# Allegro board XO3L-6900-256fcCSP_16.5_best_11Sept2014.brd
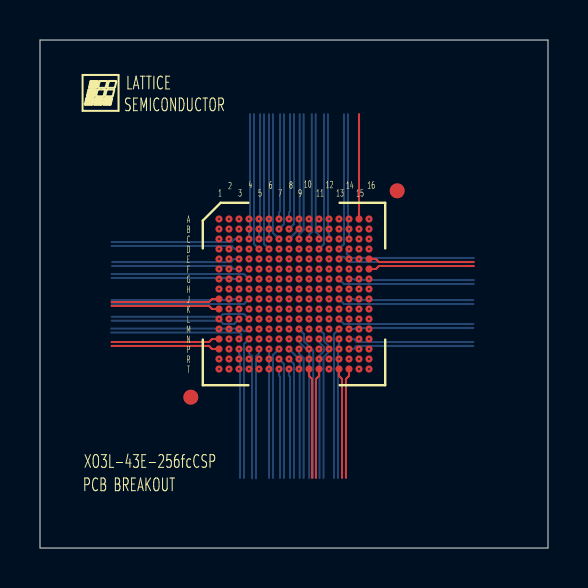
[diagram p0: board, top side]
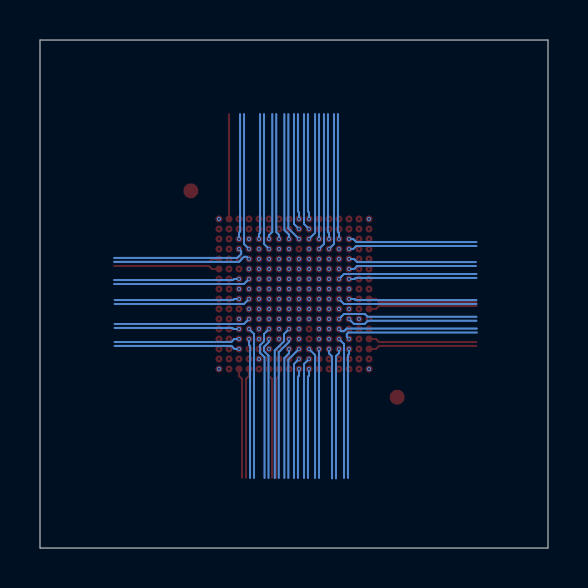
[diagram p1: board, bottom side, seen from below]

Outline 25.4 x 25.4 mm; copper layers: TOP, L2_GND, L3_SIGNAL1, L4_SIGNAL2, L5_PWR, BOTTOM. Coordinates in mm from the lower left corner of the outline.
Outline path: 0,25.4 25.4,25.4 25.4,0 0,0 0,25.4

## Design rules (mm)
constraint set DEFAULT: min track width 0.102, pair gap 0.097
net group CDPB4: nets PB4C PB4D
net group CDPB13: nets PB13C PB13D
net group CDPB18: nets PB18C PB18D
net group CDPB26: nets PB26C PB26D
net group CDPB31: nets PB31C PB31D
net group CDPB38: nets PB38C PB38D
net group CDPL2: nets PL2C PL2D
net group CDPL4: nets PL4C PL4D
net group CDPL6: nets PL6C PL6D
net group CDPL7: nets PL7C PL7D
net group CDPL9: nets PL9C PL9D
net group CDPL10: nets PL10C PL10D
net group CDPL15: nets PL15C PL15D
net group CDPL16: nets PL16C PL16D
net group CDPL19: nets PL19C PL19D
net group CDPL21: nets PL21C PL21D
net group CDPL23: nets PL23C PL23D
net group CDPL25: nets PL25C PL25D
net group CDPR2: nets PR2C PR2D
net group CDPR4: nets PR4C PR4D
net group CDPR6: nets PR6C PR6D
net group CDPR7: nets PR7C PR7D
net group CDPR10: nets PR10C PR10D
net group CDPR11: nets PR11C PR11D
net group CDPR16: nets PR16C PR16D
net group CDPR17: nets PR17C PR17D
net group CDPR19: nets PR19C PR19D
net group CDPR21: nets PR21C PR21D
net group CDPR23: nets PR23C PR23D
net group CDPR24: nets PR24A PR24B
net group CDPR25: nets PR25C PR25D
net group CDPT14: nets PT14C PT14D
net group CDPT17: nets PT17C PT17D
net group CDPT22: nets PT22C PT22D
net group CDPT27: nets PT27C PT27D
net group CDPT36: nets PT36C PT36D
net group PB4: nets PB4A PB4B
net group PB6: nets PB6A PB6B
net group PB7: nets PB7A PB7B
net group PB9: nets PB9A PB9B
net group PB10: nets PB10A PB10B
net group PB12: nets PB12A PB12B
net group PB13: nets PB13A PB13B
net group PB15: nets PB15A PB15B
net group PB16: nets PB16A PB16B
net group PB18: nets PB18A PB18B
net group PB21: nets PB21A PB21B
net group PB23: nets PB23A PB23B
net group PB26: nets PB26A PB26B
net group PB28: nets PB28A PB28B
net group PB29: nets PB29A PB29B
net group PB31: nets PB31A PB31B
net group PB34: nets PB34A PB34B
net group PB35: nets PB35A PB35B
net group PB37: nets PB37A PB37B
net group PB38: nets PB38A PB38B
net group PL3: nets PL3A PL3B
net group PL4: nets PL4A PL4B
net group PL6: nets PL6A PL6B
net group PL8: nets PL8A PL8B
net group PL9: nets PL9A PL9B
net group PL10: nets PL10A PL10B
net group PL11: nets PL11A PL11B
net group PL12: nets PL12A PL12B
net group PL15: nets PL15A PL15B
net group PL17: nets PL17A PL17B
net group PL19: nets PL19A PL19B
net group PL22: nets PL22A PL22B
net group PL24: nets PL24A PL24B
net group PL25: nets PL25A PL25B
net group PR2: nets PR2A PR2B
net group PR3: nets PR3A PR3B
net group PR5: nets PR5A PR5B
net group PR7: nets PR7A PR7B
net group PR9: nets PR9A PR9B
net group PR11: nets PR11A PR11B
net group PR12: nets PR12A PR12B
net group PR15: nets PR15A PR15B
net group PR16: nets PR16A PR16B
net group PR17: nets PR17A PR17B
net group PR18: nets PR18A PR18B
net group PR21: nets PR21A PR21B
net group PR23: nets PR23A PR23B
net group PT9: nets PT9A PT9B
net group PT10: nets PT10A PT10B
net group PT11: nets PT11A PT11B
net group PT12: nets PT12A PT12B
net group PT14: nets PT14A PT14B
net group PT15: nets PT15A PT15B
net group PT16: nets PT16A PT16B
net group PT17: nets PT17A PT17B
net group PT18: nets PT18A PT18B
net group PT21: nets PT21A PT21B
net group PT22: nets PT22A PT22B
net group PT25: nets PT25A PT25B
net group PT26: nets PT26A PT26B
net group PT27: nets PT27A PT27B
net group PT28: nets PT28A PT28B
net group PT32: nets PT32A PT32B
net group PT33: nets PT33A PT33B
net group PT34: nets PT34A PT34B
net group PT35: nets PT35A PT35B
net group PT36: nets PT36A PT36B

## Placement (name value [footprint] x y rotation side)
BGA  -  [BGA256C50P16X16_900X900X100B-1]  12.7 12.7 270 top
NOREF  -  []  1.85 21.54 0 top

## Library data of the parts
BGA = BGA256C50P16X16_900X900X100B-1

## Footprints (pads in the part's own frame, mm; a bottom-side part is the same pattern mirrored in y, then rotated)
BGA256C50P16X16_900X900X100B-1
  round 0.75 smd: (-5.16,5.16) (5.16,-5.16)
  round 0.356 smd: A1(-3.75,-3.75) A2(-3.75,-3.25) A3(-3.75,-2.75) A4(-3.75,-2.25) A5(-3.75,-1.75) A6(-3.75,-1.25) A7(-3.75,-0.75) A8(-3.75,-0.25) A9(-3.75,0.25) A10(-3.75,0.75) A11(-3.75,1.25) A12(-3.75,1.75) A13(-3.75,2.25) A14(-3.75,2.75) A15(-3.75,3.25) A16(-3.75,3.75) B1(-3.25,-3.75) B2(-3.25,-3.25) B3(-3.25,-2.75) B4(-3.25,-2.25) B5(-3.25,-1.75) B6(-3.25,-1.25) B7(-3.25,-0.75) B8(-3.25,-0.25) B9(-3.25,0.25) B10(-3.25,0.75) B11(-3.25,1.25) B12(-3.25,1.75) B13(-3.25,2.25) B14(-3.25,2.75) B15(-3.25,3.25) B16(-3.25,3.75) C1(-2.75,-3.75) C2(-2.75,-3.25) C3(-2.75,-2.75) C4(-2.75,-2.25) C5(-2.75,-1.75) C6(-2.75,-1.25) C7(-2.75,-0.75) C8(-2.75,-0.25) C9(-2.75,0.25) C10(-2.75,0.75) C11(-2.75,1.25) C12(-2.75,1.75) C13(-2.75,2.25) C14(-2.75,2.75) C15(-2.75,3.25) C16(-2.75,3.75) D1(-2.25,-3.75) D2(-2.25,-3.25) D3(-2.25,-2.75) D4(-2.25,-2.25) D5(-2.25,-1.75) D6(-2.25,-1.25) D7(-2.25,-0.75) D8(-2.25,-0.25) D9(-2.25,0.25) D10(-2.25,0.75) D11(-2.25,1.25) D12(-2.25,1.75) D13(-2.25,2.25) D14(-2.25,2.75) D15(-2.25,3.25) D16(-2.25,3.75) E1(-1.75,-3.75) E2(-1.75,-3.25) E3(-1.75,-2.75) E4(-1.75,-2.25) E5(-1.75,-1.75) E6(-1.75,-1.25) E7(-1.75,-0.75) E8(-1.75,-0.25) E9(-1.75,0.25) E10(-1.75,0.75) E11(-1.75,1.25) E12(-1.75,1.75) E13(-1.75,2.25) E14(-1.75,2.75) E15(-1.75,3.25) E16(-1.75,3.75) F1(-1.25,-3.75) F2(-1.25,-3.25) F3(-1.25,-2.75) F4(-1.25,-2.25) F5(-1.25,-1.75) F6(-1.25,-1.25) F7(-1.25,-0.75) F8(-1.25,-0.25) F9(-1.25,0.25) F10(-1.25,0.75) F11(-1.25,1.25) F12(-1.25,1.75) F13(-1.25,2.25) F14(-1.25,2.75) F15(-1.25,3.25) F16(-1.25,3.75) G1(-0.75,-3.75) G2(-0.75,-3.25) G3(-0.75,-2.75) G4(-0.75,-2.25) G5(-0.75,-1.75) G6(-0.75,-1.25) G7(-0.75,-0.75) G8(-0.75,-0.25) G9(-0.75,0.25) G10(-0.75,0.75) G11(-0.75,1.25) G12(-0.75,1.75) G13(-0.75,2.25) G14(-0.75,2.75) G15(-0.75,3.25) G16(-0.75,3.75) H1(-0.25,-3.75) H2(-0.25,-3.25) H3(-0.25,-2.75) H4(-0.25,-2.25) H5(-0.25,-1.75) H6(-0.25,-1.25) H7(-0.25,-0.75) H8(-0.25,-0.25) H9(-0.25,0.25) H10(-0.25,0.75) H11(-0.25,1.25) H12(-0.25,1.75) H13(-0.25,2.25) H14(-0.25,2.75) H15(-0.25,3.25) H16(-0.25,3.75) J1(0.25,-3.75) J2(0.25,-3.25) J3(0.25,-2.75) J4(0.25,-2.25) J5(0.25,-1.75) J6(0.25,-1.25) J7(0.25,-0.75) J8(0.25,-0.25) J9(0.25,0.25) J10(0.25,0.75) J11(0.25,1.25) J12(0.25,1.75) J13(0.25,2.25) J14(0.25,2.75) J15(0.25,3.25) J16(0.25,3.75) K1(0.75,-3.75) K2(0.75,-3.25) K3(0.75,-2.75) K4(0.75,-2.25) K5(0.75,-1.75) K6(0.75,-1.25) K7(0.75,-0.75) K8(0.75,-0.25) K9(0.75,0.25) K10(0.75,0.75) K11(0.75,1.25) K12(0.75,1.75) K13(0.75,2.25) K14(0.75,2.75) K15(0.75,3.25) K16(0.75,3.75) L1(1.25,-3.75) L2(1.25,-3.25) L3(1.25,-2.75) L4(1.25,-2.25) L5(1.25,-1.75) L6(1.25,-1.25) L7(1.25,-0.75) L8(1.25,-0.25) L9(1.25,0.25) L10(1.25,0.75) L11(1.25,1.25) L12(1.25,1.75) L13(1.25,2.25) L14(1.25,2.75) L15(1.25,3.25) L16(1.25,3.75) M1(1.75,-3.75) M2(1.75,-3.25) M3(1.75,-2.75) M4(1.75,-2.25) M5(1.75,-1.75) M6(1.75,-1.25) M7(1.75,-0.75) M8(1.75,-0.25) M9(1.75,0.25) M10(1.75,0.75) M11(1.75,1.25) M12(1.75,1.75) M13(1.75,2.25) M14(1.75,2.75) M15(1.75,3.25) M16(1.75,3.75) N1(2.25,-3.75) N2(2.25,-3.25) N3(2.25,-2.75) N4(2.25,-2.25) N5(2.25,-1.75) N6(2.25,-1.25) N7(2.25,-0.75) N8(2.25,-0.25) N9(2.25,0.25) N10(2.25,0.75) N11(2.25,1.25) N12(2.25,1.75) N13(2.25,2.25) N14(2.25,2.75) N15(2.25,3.25) N16(2.25,3.75) P1(2.75,-3.75) P2(2.75,-3.25) P3(2.75,-2.75) P4(2.75,-2.25) P5(2.75,-1.75) P6(2.75,-1.25) P7(2.75,-0.75) P8(2.75,-0.25) P9(2.75,0.25) P10(2.75,0.75) P11(2.75,1.25) P12(2.75,1.75) P13(2.75,2.25) P14(2.75,2.75) P15(2.75,3.25) P16(2.75,3.75) R1(3.25,-3.75) R2(3.25,-3.25) R3(3.25,-2.75) R4(3.25,-2.25) R5(3.25,-1.75) R6(3.25,-1.25) R7(3.25,-0.75) R8(3.25,-0.25) R9(3.25,0.25) R10(3.25,0.75) R11(3.25,1.25) R12(3.25,1.75) R13(3.25,2.25) R14(3.25,2.75) R15(3.25,3.25) R16(3.25,3.75) T1(3.75,-3.75) T2(3.75,-3.25) T3(3.75,-2.75) T4(3.75,-2.25) T5(3.75,-1.75) T6(3.75,-1.25) T7(3.75,-0.75) T8(3.75,-0.25) T9(3.75,0.25) T10(3.75,0.75) T11(3.75,1.25) T12(3.75,1.75) T13(3.75,2.25) T14(3.75,2.75) T15(3.75,3.25) T16(3.75,3.75)

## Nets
GND: BGA.A1 BGA.A16 BGA.F5 BGA.F10 BGA.G7 BGA.G8 BGA.G9 BGA.G10 BGA.G11 BGA.H6 BGA.H11 BGA.J6 BGA.J11 BGA.K5 BGA.K6 BGA.K7 BGA.K8 BGA.K9 BGA.K10 BGA.K11 BGA.K12 BGA.L6 BGA.T1 BGA.T16
VCC: BGA.H7 BGA.H8 BGA.H9 BGA.H10 BGA.J7 BGA.J8 BGA.J9 BGA.J10
VCCIO0: BGA.F6 BGA.F7 BGA.F8 BGA.F9
VCCIO1: BGA.G6 BGA.H5 BGA.J5
VCCIO2: BGA.L7 BGA.L8 BGA.L9 BGA.L10
VCCIO3: BGA.L11 BGA.L12
VCCIO4: BGA.H12 BGA.J12
VCCIO5: BGA.F11 BGA.G12
PB4A: BGA.P13
PB4B: BGA.R14
PB4C: BGA.N12
PB4D: BGA.M12
PB6A: BGA.T13
PB6B: BGA.T14
PB7A: BGA.P12
PB7B: BGA.R13
PB9A: BGA.M11
PB9B: BGA.N11
PB10A: BGA.R12
PB10B: BGA.P11
PB12A: BGA.T12
PB12B: BGA.R11
PB13A: BGA.N10
PB13B: BGA.M10
PB13C: BGA.P10
PB13D: BGA.R10
PB15A: BGA.T11
PB15B: BGA.T10
PB16A: BGA.T9
PB16B: BGA.R9
PB18A: BGA.N9
PB18B: BGA.M9
PB18C: BGA.P9
PB18D: BGA.P8
PB21A: BGA.R8
PB21B: BGA.T8
PB23A: BGA.T7
PB23B: BGA.R7
PB26A: BGA.N8
PB26B: BGA.M8
PB26C: BGA.T6
PB26D: BGA.R6
PB28A: BGA.P7
PB28B: BGA.P6
PB29A: BGA.T5
PB29B: BGA.R5
PB31A: BGA.N7
PB31B: BGA.M7
PB31C: BGA.T4
PB31D: BGA.R4
PB34A: BGA.R3
PB34B: BGA.T3
PB35A: BGA.M6
PB35B: BGA.N6
PB37A: BGA.R2
PB37B: BGA.T2
PB38A: BGA.M5
PB38B: BGA.N5
PB38C: BGA.P5
PB38D: BGA.P4
PL2C: BGA.D13
PL2D: BGA.C14
PL3A: BGA.B15
PL3B: BGA.B16
PL4A: BGA.C15
PL4B: BGA.C16
PL4C: BGA.D14
PL4D: BGA.E13
PL6A: BGA.D15
PL6B: BGA.D16
PL6C: BGA.F13
PL6D: BGA.F12
PL7C: BGA.E15
PL7D: BGA.E14
PL8A: BGA.G13
PL8B: BGA.G14
PL9A: BGA.F14
PL9B: BGA.F15
PL9C: BGA.E16
PL9D: BGA.F16
PL10A: BGA.G15
PL10B: BGA.G16
PL10C: BGA.H13
PL10D: BGA.H14
PL11A: BGA.H15
PL11B: BGA.H16
PL12A: BGA.J16
PL12B: BGA.J15
PL15A: BGA.K16
PL15B: BGA.K15
PL15C: BGA.J13
PL15D: BGA.J14
PL16C: BGA.L16
PL16D: BGA.K14
PL17A: BGA.M16
PL17B: BGA.L15
PL19A: BGA.N16
PL19B: BGA.M15
PL19C: BGA.K13
PL19D: BGA.L14
PL21C: BGA.M14
PL21D: BGA.L13
PL22A: BGA.P16
PL22B: BGA.N15
PL23C: BGA.P15
PL23D: BGA.R16
PL24A: BGA.R15
PL24B: BGA.T15
PL25A: BGA.M13
PL25B: BGA.N13
PL25C: BGA.N14
PL25D: BGA.P14
PR2A: BGA.A2
PR2B: BGA.B2
PR2C: BGA.D4
PR2D: BGA.E4
PR3A: BGA.B1
PR3B: BGA.C2
PR4C: BGA.D3
PR4D: BGA.C3
PR5A: BGA.D2
PR5B: BGA.C1
PR6C: BGA.F4
PR6D: BGA.G5
PR7A: BGA.D1
PR7B: BGA.E2
PR7C: BGA.F3
PR7D: BGA.E3
PR9A: BGA.G4
PR9B: BGA.G3
PR10C: BGA.E1
PR10D: BGA.F2
PR11A: BGA.G2
PR11B: BGA.F1
PR11C: BGA.H4
PR11D: BGA.H3
PR12A: BGA.H2
PR12B: BGA.G1
PR15A: BGA.H1
PR15B: BGA.J2
PR16A: BGA.J1
PR16B: BGA.K1
PR16C: BGA.J4
PR16D: BGA.J3
PR17A: BGA.K2
PR17B: BGA.L1
PR17C: BGA.L2
PR17D: BGA.K3
PR18A: BGA.M1
PR18B: BGA.M2
PR19C: BGA.K4
PR19D: BGA.L5
PR21A: BGA.N1
PR21B: BGA.P1
PR21C: BGA.L3
PR21D: BGA.L4
PR23A: BGA.M3
PR23B: BGA.N2
PR23C: BGA.R1
PR23D: BGA.P2
PR24A: BGA.N3
PR24B: BGA.M4
PR25C: BGA.P3
PR25D: BGA.N4
PT9A: BGA.A14
PT9B: BGA.B14
PT9C: BGA.A15
PT10A: BGA.E12
PT10B: BGA.E11
PT11A: BGA.A13
PT11B: BGA.B13
PT12A: BGA.C13
PT12B: BGA.D12
PT14A: BGA.E10
PT14B: BGA.D10
PT14C: BGA.D11
PT14D: BGA.C12
PT15A: BGA.B12
PT15B: BGA.A12
PT16A: BGA.A11
PT16B: BGA.B11
PT17A: BGA.B10
PT17B: BGA.A10
PT17C: BGA.C10
PT17D: BGA.C11
PT18A: BGA.B9
PT18B: BGA.A9
PT21A: BGA.E9
PT21B: BGA.D9
PT22A: BGA.C9
PT22B: BGA.C8
PT22C: BGA.A8
PT22D: BGA.B8
PT25A: BGA.D8
PT25B: BGA.E8
PT26A: BGA.B7
PT26B: BGA.A7
PT27A: BGA.D7
PT27B: BGA.E7
PT27C: BGA.C7
PT27D: BGA.C6
PT28A: BGA.A6
PT28B: BGA.B6
PT32A: BGA.A5
PT32B: BGA.B5
PT33A: BGA.D6
PT33B: BGA.C5
PT34A: BGA.E6
PT34B: BGA.E5
PT35A: BGA.A4
PT35B: BGA.B4
PT36A: BGA.A3
PT36B: BGA.B3
PT36C: BGA.C4
PT36D: BGA.D5

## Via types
v1: diameter 0.203, hole 0.102, TOP to BOTTOM, 148 vias
v2: diameter 0.203, hole 0.102, TOP to L3_SIGNAL1, 97 vias

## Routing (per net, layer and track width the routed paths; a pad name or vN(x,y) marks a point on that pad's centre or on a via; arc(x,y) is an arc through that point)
GND:
  vias: v1(8.95,16.45) v1(8.95,8.95) v1(10.95,13.95) v1(10.95,11.95) v1(11.45,12.95) v1(11.45,12.45) v1(11.45,11.95) v1(11.45,11.45) v1(11.95,13.45) v1(11.95,11.95) v1(12.45,13.45) v1(12.45,11.95) v1(12.95,13.45) v1(12.95,11.95) v1(13.45,13.95) v1(13.45,13.45) v1(13.45,11.95) v1(13.95,13.45) v1(13.95,12.95) v1(13.95,12.45) v1(13.95,11.95) v1(14.45,11.95) v1(16.45,16.45) v1(16.45,8.95)
VCC:
  vias: v1(11.95,12.95) v1(11.95,12.45) v1(12.45,12.95) v1(12.45,12.45) v1(12.95,12.95) v1(12.95,12.45) v1(13.45,12.95) v1(13.45,12.45)
VCCIO0:
  vias: v1(11.45,13.95) v1(11.95,13.95) v1(12.45,13.95) v1(12.95,13.95)
VCCIO1:
  vias: v1(10.95,12.95) v1(10.95,12.45) v1(11.45,13.45)
VCCIO2:
  vias: v1(11.95,11.45) v1(12.45,11.45) v1(12.95,11.45) v1(13.45,11.45)
VCCIO3:
  vias: v1(13.95,11.45) v1(14.45,11.45)
VCCIO4:
  vias: v1(14.45,12.95) v1(14.45,12.45)
VCCIO5:
  vias: v1(13.95,13.95) v1(14.45,13.45)
PB4A: length 6.5
  L3_SIGNAL1 w0.102: 15.2,3.51 15.2,9.7 v2(14.95,9.95)
PB4B: length 6
  L3_SIGNAL1 w0.102: 15.4,3.51 15.4,9.07 15.45,9.12 v2(15.45,9.45)
PB4C: length 7.4
  L4_SIGNAL2 w0.102: 21.67,10.39 15.91,10.39 15.71,10.2 14.7,10.2 v1(14.45,10.45)
PB4D: length 7.4
  L4_SIGNAL2 w0.102: 21.67,10.59 15.82,10.59 15.72,10.7 14.7,10.7 v1(14.45,10.95)
PB6A: length 5.5
  TOP w0.102: BGA.T13 14.95,8.6 15.1,8.45 15.1,3.51
PB6B: length 5.5
  TOP w0.102: BGA.T14 15.45,8.61 15.3,8.45 15.3,3.51
PB7A: length 6.6
  L3_SIGNAL1 w0.102: 14.75,3.51 14.75,9.12 14.7,9.17 14.7,9.7 v2(14.45,9.95)
PB7B: length 5.9
  L3_SIGNAL1 w0.102: v2(14.95,9.45) 14.95,3.51
PB9A: length 7.7
  BOTTOM w0.102: v1(13.95,10.95) 14.2,10.7 14.2,10.33 14.4,10.14 14.4,9.76 14.17,9.54 14.17,3.51
PB9B: length 7.1
  BOTTOM w0.102: v1(13.95,10.45) 13.95,10.3 14.2,10.05 14.2,9.85 13.98,9.62 13.98,3.51
PB10A: length 6.4
  L4_SIGNAL2 w0.102: v1(14.45,9.45) 14.34,9.56 14.2,9.56 14.02,9.38 14.02,3.53
PB10B: length 6.6
  L4_SIGNAL2 w0.102: v1(13.95,9.95) 14.06,9.84 14.06,9.7 13.82,9.46 13.82,3.53
PB12A: length 5.9
  L3_SIGNAL1 w0.102: v2(14.45,8.95) 14.34,9.06 14.2,9.06 14.13,8.99 14.13,3.51
PB12B: length 6
  L3_SIGNAL1 w0.102: 13.93,3.51 13.93,9.07 14.06,9.2 14.06,9.34 v2(13.95,9.45)
PB13A: length 6.9
  L4_SIGNAL2 w0.102: 13.4,3.53 13.4,10.06 13.45,10.11 v1(13.45,10.45)
PB13B: length 7.5
  L4_SIGNAL2 w0.102: v1(13.45,10.95) 13.2,10.7 13.2,3.53
PB13C: length 6.5
  L3_SIGNAL1 w0.102: 13.7,3.51 13.7,9.7 v2(13.45,9.95)
PB13D: length 6
  L3_SIGNAL1 w0.102: v2(13.45,9.45) 13.45,9.12 13.5,9.07 13.5,3.51
PB15A: length 5.5
  TOP w0.102: BGA.T11 13.95,8.61 13.8,8.45 13.8,3.51
PB15B: length 5.5
  TOP w0.102: BGA.T10 13.45,8.61 13.6,8.45 13.6,3.51
PB16A: length 5.5
  L3_SIGNAL1 w0.102: v2(12.95,8.95) 12.95,8.62 13,8.57 13,3.51
PB16B: length 6
  L3_SIGNAL1 w0.102: v2(12.95,9.45) 13.2,9.2 13.2,3.51
PB18A: length 7.2
  BOTTOM w0.102: v1(12.95,10.45) 12.95,10.3 13.46,9.79 13.46,3.51
PB18B: length 7.7
  BOTTOM w0.102: v1(12.95,10.95) 13.2,10.7 13.2,10.33 13.66,9.87 13.66,3.51
PB18C: length 6.5
  BOTTOM w0.102: 13.18,3.51 13.18,9.5 12.95,9.73 v1(12.95,9.95)
PB18D: length 6.7
  BOTTOM w0.102: v1(12.45,9.95) 12.98,9.42 12.98,3.51
PB21A: length 6
  BOTTOM w0.102: v1(12.45,9.45) 12.7,9.2 12.7,3.51
PB21B: length 5.5
  BOTTOM w0.102: 12.5,3.51 12.5,8.57 12.45,8.62 v1(12.45,8.95)
PB23A: length 5.5
  BOTTOM w0.102: v1(11.95,8.95) 11.95,8.62 12,8.57 12,3.51
PB23B: length 6
  BOTTOM w0.102: v1(11.95,9.45) 12.2,9.2 12.2,3.51
PB26A: length 7.1
  L4_SIGNAL2 w0.102: 12.6,3.51 12.6,8.53 12.7,8.64 12.7,10.2 v1(12.45,10.45)
PB26B: length 7.6
  L4_SIGNAL2 w0.102: 12.4,3.51 12.4,8.53 12.2,8.73 12.2,10.7 v1(12.45,10.95)
PB26C: length 5.5
  L3_SIGNAL1 w0.102: v2(11.45,8.95) 11.45,8.62 11.5,8.57 11.5,3.51
PB26D: length 6
  L3_SIGNAL1 w0.102: v2(11.45,9.45) 11.7,9.2 11.7,3.51
PB28A: length 6.6
  BOTTOM w0.102: 11.65,3.51 11.65,9.65 v1(11.95,9.95)
PB28B: length 6.4
  BOTTOM w0.102: 11.45,3.51 v1(11.45,9.95)
PB29A: length 5.5
  L3_SIGNAL1 w0.102: v2(10.95,8.95) 10.95,8.62 11,8.57 11,3.51
PB29B: length 6
  L3_SIGNAL1 w0.102: 11.2,3.51 11.2,9.2 v2(10.95,9.45)
PB31A: length 7.1
  L3_SIGNAL1 w0.102: v2(11.95,10.45) 12.2,10.2 12.2,8.6 12.29,8.51 12.29,3.51
PB31B: length 8.1
  L3_SIGNAL1 w0.102: 12.49,3.51 12.49,8.5 12.7,8.71 12.7,10.57 12.57,10.7 12.2,10.7 v2(11.95,10.95)
PB31C: length 5.5
  L3_SIGNAL1 w0.102: v2(10.45,8.95) 10.45,8.62 10.5,8.57 10.5,3.51
PB31D: length 6
  L3_SIGNAL1 w0.102: 10.7,3.51 10.7,9.2 v2(10.45,9.45)
PB34A: length 6
  L3_SIGNAL1 w0.102: v2(9.95,9.45) 10.2,9.2 10.2,3.51
PB34B: length 5.5
  L3_SIGNAL1 w0.102: 10,3.51 10,8.57 9.95,8.62 v2(9.95,8.95)
PB35A: length 7.6
  L4_SIGNAL2 w0.102: 11.35,3.51 11.35,9.55 11.2,9.7 11.2,10.7 v1(11.45,10.95)
PB35B: length 7.1
  L4_SIGNAL2 w0.102: v1(11.45,10.45) 11.7,10.2 11.7,9.72 11.55,9.57 11.55,3.51
PB37A: length 6
  L3_SIGNAL1 w0.102: v2(9.45,9.45) 9.7,9.2 9.7,3.51
PB37B: length 5.5
  L3_SIGNAL1 w0.102: 9.5,3.51 9.5,8.57 9.45,8.62 v2(9.45,8.95)
PB38A: length 8
  L4_SIGNAL2 w0.102: 10.35,3.51 10.35,9.56 10.2,9.71 10.2,10.55 10.35,10.7 10.7,10.7 v1(10.95,10.95)
PB38B: length 7.1
  L4_SIGNAL2 w0.102: v1(10.95,10.45) 10.7,10.2 10.7,9.73 10.55,9.58 10.55,3.51
PB38C: length 6.5
  BOTTOM w0.102: v1(10.95,9.95) 10.95,9.73 10.8,9.58 10.8,3.48
PB38D: length 6.5
  BOTTOM w0.102: 10.6,3.48 10.6,9.59 10.45,9.74 v1(10.45,9.95)
PL2C: length 6.8
  BOTTOM w0.102: 15.2,21.69 15.2,15.2 v1(14.95,14.95)
PL2D: length 6.3
  BOTTOM w0.102: 15.4,21.69 15.4,15.82 15.45,15.77 v1(15.45,15.45)
PL3A: length 5.8
  L3_SIGNAL1 w0.102: 21.69,16.2 16.2,16.2 v2(15.95,15.95)
PL3B: length 5.3
  L3_SIGNAL1 w0.102: 21.69,16 16.83,16 16.78,15.95 v2(16.45,15.95)
PL4A: length 5.8
  L3_SIGNAL1 w0.102: v2(15.95,15.45) 16.2,15.7 21.69,15.7
PL4B: length 5.3
  L3_SIGNAL1 w0.102: v2(16.45,15.45) 16.78,15.45 16.83,15.5 21.69,15.5
PL4C: length 6.7
  BOTTOM w0.102: 21.69,14.5 15.54,14.5 15.34,14.7 15.34,14.84 v1(15.45,14.95)
PL4D: length 6.9
  BOTTOM w0.102: 21.69,14.31 15.45,14.31 15.2,14.56 15.06,14.56 v1(14.95,14.45)
PL6A: length 5.8
  L3_SIGNAL1 w0.102: v2(15.95,14.95) 16.2,15.2 21.69,15.2
PL6B: length 5.3
  L3_SIGNAL1 w0.102: v2(16.45,14.95) 16.78,14.95 16.83,15 21.69,15
PL6C: length 6.7
  L4_SIGNAL2 w0.102: 21.67,13.9 15.37,13.9 15.32,13.95 v1(14.95,13.95)
PL6D: length 7.3
  L4_SIGNAL2 w0.102: v1(14.45,13.95) 14.7,13.7 21.67,13.7
PL7C: length 5.7
  L3_SIGNAL1 w0.102: v2(15.95,14.45) 21.69,14.45
PL7D: length 6.4
  L3_SIGNAL1 w0.102: 21.69,14.65 16.26,14.65 16.21,14.7 15.7,14.7 v2(15.45,14.45)
PL8A: length 6.8
  BOTTOM w0.102: 21.69,13.2 15.2,13.2 v1(14.95,13.45)
PL8B: length 6.3
  BOTTOM w0.102: v1(15.45,13.45) 15.7,13.45 15.75,13.4 21.69,13.4
PL9A: length 6.3
  L3_SIGNAL1 w0.102: v2(15.45,13.95) 15.7,14.2 21.69,14.2
PL9B: length 5.8
  L3_SIGNAL1 w0.102: v2(15.95,13.95) 16.28,13.95 16.33,14 21.69,14
PL9C: length 5.3
  TOP w0.102: BGA.E16 16.79,14.45 16.95,14.3 21.69,14.3
PL9D: length 5.3
  TOP w0.102: BGA.F16 16.8,13.95 16.95,14.1 21.69,14.1
PL10A: length 5.8
  L3_SIGNAL1 w0.102: 21.69,13.7 16.2,13.7 v2(15.95,13.45)
PL10B: length 5.3
  L3_SIGNAL1 w0.102: 21.69,13.5 16.83,13.5 16.78,13.45 v2(16.45,13.45)
PL10C: length 6.8
  L4_SIGNAL2 w0.102: v1(14.95,12.95) 15.2,12.7 21.67,12.7
PL10D: length 6.2
  L4_SIGNAL2 w0.102: 21.67,12.9 15.88,12.9 15.82,12.95 v1(15.45,12.95)
PL11A: length 5.8
  L3_SIGNAL1 w0.102: v2(15.95,12.95) 16.2,13.2 21.69,13.2
PL11B: length 5.3
  L3_SIGNAL1 w0.102: v2(16.45,12.95) 16.78,12.95 16.83,13 21.69,13
PL12A: length 5.3
  L3_SIGNAL1 w0.102: 21.69,12.5 16.83,12.5 16.78,12.45 v2(16.45,12.45)
PL12B: length 5.8
  L3_SIGNAL1 w0.102: 21.69,12.7 16.2,12.7 v2(15.95,12.45)
PL15A: length 5.3
  L3_SIGNAL1 w0.102: 21.69,12 16.83,12 16.78,11.95 v2(16.45,11.95)
PL15B: length 5.8
  L3_SIGNAL1 w0.102: 21.69,12.2 16.2,12.2 v2(15.95,11.95)
PL15C: length 6.8
  BOTTOM w0.102: 21.67,12.2 15.2,12.2 v1(14.95,12.45)
PL15D: length 6.2
  BOTTOM w0.102: v1(15.45,12.45) 15.69,12.45 15.74,12.4 21.67,12.4
PL16C: length 5.3
  L3_SIGNAL1 w0.102: 21.69,11.5 16.84,11.5 16.79,11.45 v2(16.45,11.45)
PL16D: length 6.3
  L3_SIGNAL1 w0.102: 21.69,11.7 15.7,11.7 v2(15.45,11.95)
PL17A: length 5.3
  L3_SIGNAL1 w0.102: v2(16.45,10.95) 16.78,10.95 16.83,11 21.69,11
PL17B: length 5.8
  L3_SIGNAL1 w0.102: v2(15.95,11.45) 16.2,11.2 21.69,11.2
PL19A: length 5.3
  L3_SIGNAL1 w0.102: 21.69,10.5 16.83,10.5 16.78,10.45 v2(16.45,10.45)
PL19B: length 5.8
  L3_SIGNAL1 w0.102: 21.69,10.7 16.2,10.7 v2(15.95,10.95)
PL19C: length 6.9
  L4_SIGNAL2 w0.102: v1(14.95,11.95) 15.06,11.84 15.2,11.84 15.45,12.09 21.67,12.09
PL19D: length 6.7
  L4_SIGNAL2 w0.102: v1(15.45,11.45) 15.34,11.56 15.34,11.7 15.53,11.89 21.67,11.89
PL21C: length 6.2
  BOTTOM w0.102: 21.67,11 15.78,11 15.73,10.95 v1(15.45,10.95)
PL21D: length 6.8
  BOTTOM w0.102: v1(14.95,11.45) 15.2,11.2 21.67,11.2
PL22A: length 5.3
  L3_SIGNAL1 w0.102: v2(16.45,9.95) 16.78,9.95 16.83,10 21.69,10
PL22B: length 5.8
  L3_SIGNAL1 w0.102: 21.69,10.2 16.2,10.2 v2(15.95,10.45)
PL23C: length 5.8
  L3_SIGNAL1 w0.102: 21.69,9.7 16.2,9.7 v2(15.95,9.95)
PL23D: length 5.3
  L3_SIGNAL1 w0.102: 21.69,9.5 16.83,9.5 16.78,9.45 v2(16.45,9.45)
PL24A: length 6
  L3_SIGNAL1 w0.102: v2(15.95,9.45) 16.2,9.2 16.2,3.51
PL24B: length 5.5
  L3_SIGNAL1 w0.102: v2(15.95,8.95) 15.95,8.62 16,8.57 16,3.51
PL25A: length 7.5
  BOTTOM w0.102: v1(14.95,10.95) 14.7,10.7 14.7,3.51
PL25B: length 7
  BOTTOM w0.102: 14.9,3.51 14.9,10.11 14.95,10.16 v1(14.95,10.45)
PL25C: length 6.3
  BOTTOM w0.102: v1(15.45,10.45) 15.69,10.45 15.84,10.3 21.67,10.3
PL25D: length 6.3
  BOTTOM w0.102: 21.67,10.1 15.82,10.1 15.67,9.95 v1(15.45,9.95)
PR2A: length 5.3
  L3_SIGNAL1 w0.102: v2(9.45,16.45) 9.45,16.78 9.5,16.83 9.5,21.69
PR2B: length 5.8
  L3_SIGNAL1 w0.102: 9.7,21.69 9.7,16.2 v2(9.45,15.95)
PR2C: length 7
  L4_SIGNAL2 w0.102: v1(10.45,14.95) 10.2,15.2 9.76,15.2 9.6,15.04 3.58,15.04
PR2D: length 7
  L4_SIGNAL2 w0.102: v1(10.45,14.45) 10.2,14.7 9.73,14.7 9.6,14.84 3.58,14.84
PR3A: length 5.4
  L3_SIGNAL1 w0.102: 3.58,15.9 5.45,15.9 8.57,15.9 8.62,15.95 v2(8.95,15.95)
PR3B: length 6
  L3_SIGNAL1 w0.102: 3.58,15.7 5.53,15.7 9.2,15.7 v2(9.45,15.45)
PR4C: length 6.4
  BOTTOM w0.102: 3.58,15.1 9.59,15.1 9.74,14.95 v1(9.95,14.95)
PR4D: length 6.4
  BOTTOM w0.102: v1(9.95,15.45) 9.74,15.45 9.58,15.3 3.58,15.3
PR5A: length 6
  L3_SIGNAL1 w0.102: v2(9.45,14.95) 9.2,15.2 5.74,15.2 5.74,15.2 3.58,15.2
PR5B: length 5.4
  L3_SIGNAL1 w0.102: v2(8.95,15.45) 8.62,15.45 8.57,15.4 6.07,15.4 5.66,15.4 3.58,15.4
PR6C: length 7
  L4_SIGNAL2 w0.102: 3.58,14.06 9.58,14.06 9.73,14.2 10.2,14.2 v1(10.45,13.95)
PR6D: length 7.5
  L4_SIGNAL2 w0.102: 3.58,13.86 9.57,13.86 9.73,13.7 10.7,13.7 v1(10.95,13.45)
PR7A: length 5.4
  L3_SIGNAL1 w0.102: v2(8.95,14.95) 8.62,14.95 8.57,14.9 5.87,14.9 3.58,14.9
PR7B: length 6
  L3_SIGNAL1 w0.102: 3.58,14.7 5.95,14.7 9.2,14.7 v2(9.45,14.45)
PR7C: length 6.4
  BOTTOM w0.102: v1(9.95,13.95) 9.7,13.95 9.55,14.1 3.61,14.1
PR7D: length 6.4
  BOTTOM w0.102: v1(9.95,14.45) 9.7,14.45 9.55,14.3 3.61,14.3
PR9A: length 7
  BOTTOM w0.102: 3.58,13.7 10.2,13.7 v1(10.45,13.45)
PR9B: length 6.4
  BOTTOM w0.102: v1(9.95,13.45) 9.68,13.45 9.63,13.5 3.58,13.5
PR10C: length 5.4
  L3_SIGNAL1 w0.102: 3.58,14.4 6.07,14.4 8.57,14.4 8.62,14.45 v2(8.95,14.45)
PR10D: length 6
  L3_SIGNAL1 w0.102: 3.58,14.2 9.2,14.2 v2(9.45,13.95)
PR11A: length 6
  L3_SIGNAL1 w0.102: 3.58,13.7 9.2,13.7 v2(9.45,13.45)
PR11B: length 5.4
  L3_SIGNAL1 w0.102: 3.58,13.9 8.57,13.9 8.62,13.95 v2(8.95,13.95)
PR11C: length 6.9
  L4_SIGNAL2 w0.102: v1(10.45,12.95) 10.2,13.2 3.61,13.2
PR11D: length 6.4
  L4_SIGNAL2 w0.102: v1(9.95,12.95) 9.61,12.95 9.55,13 3.61,13
PR12A: length 6
  L3_SIGNAL1 w0.102: v2(9.45,12.95) 9.2,13.2 3.58,13.2
PR12B: length 5.4
  L3_SIGNAL1 w0.102: v2(8.95,13.45) 8.62,13.45 8.57,13.4 3.58,13.4
PR15A: length 5.8
  L3_SIGNAL1 w0.102: v2(8.95,12.95) 9.06,12.84 9.06,12.7 8.99,12.63 3.58,12.63
PR15B: length 6
  L3_SIGNAL1 w0.102: 3.58,12.43 9.07,12.43 9.2,12.56 9.34,12.56 v2(9.45,12.45)
PR16A: length 5.4
  TOP w0.102: 3.58,12.3 8.45,12.3 8.6,12.45 BGA.J1
PR16B: length 5.4
  TOP w0.102: BGA.K1 8.61,11.95 8.45,12.1 3.58,12.1
PR16C: length 7
  BOTTOM w0.102: 3.58,12.2 10.2,12.2 v1(10.45,12.45)
PR16D: length 6.4
  BOTTOM w0.102: v1(9.95,12.45) 9.68,12.45 9.63,12.4 3.58,12.4
PR17A: length 6
  L3_SIGNAL1 w0.102: 3.58,11.97 9.07,11.97 9.13,11.91 9.2,11.84 9.34,11.84 v2(9.45,11.95)
PR17B: length 5.8
  L3_SIGNAL1 w0.102: v2(8.95,11.45) 9.06,11.56 9.06,11.7 8.99,11.77 3.58,11.77
PR17C: length 6.3
  L4_SIGNAL2 w0.102: 3.58,11.86 9.4,11.86 9.56,11.7 9.56,11.56 v1(9.45,11.45)
PR17D: length 6.5
  L4_SIGNAL2 w0.102: v1(9.95,11.95) 9.84,11.84 9.7,11.84 9.48,12.06 3.58,12.06
PR18A: length 5.4
  L3_SIGNAL1 w0.102: 3.58,11 8.57,11 8.62,10.95 v2(8.95,10.95)
PR18B: length 6
  L3_SIGNAL1 w0.102: v2(9.45,10.95) 9.2,11.2 3.58,11.2
PR19C: length 7.4
  L4_SIGNAL2 w0.102: 3.58,11.1 9.95,11.1 10.2,11.35 10.2,11.7 v1(10.45,11.95)
PR19D: length 7.6
  L4_SIGNAL2 w0.102: v1(10.95,11.45) 10.7,11.2 10.33,11.2 10.04,10.9 3.58,10.9
PR21A: length 5.4
  TOP w0.102: 3.58,10.3 8.45,10.3 8.6,10.45 BGA.N1
PR21B: length 5.4
  TOP w0.102: 3.58,10.1 8.45,10.1 8.61,9.95 BGA.P1
PR21C: length 6.5
  BOTTOM w0.102: 3.58,11.36 9.01,11.36 9.17,11.2 9.35,11.2 9.35,11.2 9.55,11.2 9.55,11.2 9.7,11.2 v1(9.95,11.45)
PR21D: length 7
  BOTTOM w0.102: 3.58,11.56 9.02,11.56 9.16,11.7 10.2,11.7 v1(10.45,11.45)
PR23A: length 6.5
  L3_SIGNAL1 w0.102: 3.58,10.65 9.12,10.65 9.17,10.7 9.7,10.7 v2(9.95,10.95)
PR23B: length 5.9
  L3_SIGNAL1 w0.102: v2(9.45,10.45) 3.58,10.45
PR23C: length 5.8
  L3_SIGNAL1 w0.102: 3.58,9.78 8.98,9.78 9.06,9.7 9.06,9.56 v2(8.95,9.45)
PR23D: length 6
  L3_SIGNAL1 w0.102: 3.58,9.98 9.06,9.98 9.2,9.84 9.34,9.84 v2(9.45,9.95)
PR24A: length 6.8
  BOTTOM w0.102: 3.56,10.77 9.99,10.77 10.06,10.7 10.06,10.56 v1(9.95,10.45)
PR24B: length 7
  BOTTOM w0.102: 3.56,10.97 10.07,10.97 10.2,10.84 10.34,10.84 v1(10.45,10.95)
PR25C: length 6.5
  BOTTOM w0.102: 10,3.51 10,9.65 9.95,9.7 v1(9.95,9.95)
PR25D: length 7
  BOTTOM w0.102: 10.2,3.51 10.2,10.2 v1(10.45,10.45)
PT9A: length 5.3
  L3_SIGNAL1 w0.102: v2(15.45,16.45) 15.45,16.78 15.5,16.83 15.5,21.69
PT9B: length 5.8
  L3_SIGNAL1 w0.102: v2(15.45,15.95) 15.7,16.2 15.7,21.69
PT9C: length 5.2
  TOP w0.102: BGA.A15 15.95,21.69
PT10A: length 7.4
  L4_SIGNAL2 w0.102: v1(14.45,14.45) 14.7,14.2 15.19,14.2 15.34,14.35 21.67,14.35
PT10B: length 7.9
  L4_SIGNAL2 w0.102: 21.67,14.55 15.37,14.55 15.22,14.7 14.35,14.7 14.1,14.45 v1(13.95,14.45)
PT11A: length 5.3
  L3_SIGNAL1 w0.102: v2(14.95,16.45) 14.95,16.78 15,16.83 15,21.69
PT11B: length 5.8
  L3_SIGNAL1 w0.102: v2(14.95,15.95) 15.2,16.2 15.2,21.69
PT12A: length 6.3
  L4_SIGNAL2 w0.102: 14.9,21.69 14.9,15.8 14.95,15.75 v1(14.95,15.45)
PT12B: length 6.8
  L4_SIGNAL2 w0.102: v1(14.45,14.95) 14.7,15.2 14.7,21.69
PT14A: length 7.8
  L4_SIGNAL2 w0.102: 14.05,21.69 14.05,15.82 14.2,15.67 14.2,14.85 14.05,14.7 13.7,14.7 v1(13.45,14.45)
PT14B: length 6.9
  L4_SIGNAL2 w0.102: 13.86,21.69 13.86,15.84 13.7,15.68 13.7,15.2 v1(13.45,14.95)
PT14C: length 6.8
  BOTTOM w0.102: v1(13.95,14.95) 14.2,15.2 14.2,21.69
PT14D: length 6.3
  BOTTOM w0.102: v1(14.45,15.45) 14.45,15.7 14.4,15.75 14.4,21.69
PT15A: length 5.8
  L3_SIGNAL1 w0.102: v2(14.45,15.95) 14.7,16.2 14.7,21.69
PT15B: length 5.3
  L3_SIGNAL1 w0.102: v2(14.45,16.45) 14.45,16.78 14.5,16.83 14.5,21.69
PT16A: length 5.3
  L3_SIGNAL1 w0.102: v2(13.95,16.45) 13.95,16.78 14,16.83 14,21.69
PT16B: length 5.8
  L3_SIGNAL1 w0.102: 14.2,21.69 14.2,16.2 v2(13.95,15.95)
PT17A: length 5.8
  L3_SIGNAL1 w0.102: v2(13.45,15.95) 13.7,16.2 13.7,21.69
PT17B: length 5.3
  L3_SIGNAL1 w0.102: 13.5,21.69 13.5,16.83 13.45,16.78 v2(13.45,16.45)
PT17C: length 6.3
  BOTTOM w0.102: v1(13.45,15.45) 13.45,15.66 13.59,15.8 13.59,21.69
PT17D: length 6.3
  BOTTOM w0.102: v1(13.95,15.45) 13.95,15.64 13.79,15.8 13.79,21.69
PT18A: length 5.8
  L3_SIGNAL1 w0.102: 13.2,21.69 13.2,16.2 v2(12.95,15.95)
PT18B: length 5.3
  L3_SIGNAL1 w0.102: 13,21.69 13,16.83 12.95,16.78 v2(12.95,16.45)
PT21A: length 7.4
  L4_SIGNAL2 w0.102: 12.84,21.69 12.84,15.84 12.7,15.7 12.7,14.7 v1(12.95,14.45)
PT21B: length 6.9
  L4_SIGNAL2 w0.102: 13.04,21.69 13.04,15.84 13.2,15.68 13.2,15.2 v1(12.95,14.95)
PT22A: length 6.3
  BOTTOM w0.102: v1(12.95,15.45) 12.95,15.67 13.18,15.9 13.18,21.69
PT22B: length 6.5
  BOTTOM w0.102: 12.98,21.69 12.98,15.98 v1(12.45,15.45)
PT22C: length 5.3
  BOTTOM w0.102: v1(12.45,16.45) 12.45,16.78 12.5,16.83 12.5,21.69
PT22D: length 5.8
  BOTTOM w0.102: v1(12.45,15.95) 12.7,16.2 12.7,21.69
PT25A: length 6.9
  L3_SIGNAL1 w0.102: v2(12.45,14.95) 12.2,15.2 12.2,16.75 12.35,16.9 12.35,21.69
PT25B: length 7.4
  L3_SIGNAL1 w0.102: 12.55,21.69 12.55,16.89 12.7,16.74 12.7,14.7 v1(12.45,14.45)
PT26A: length 5.8
  BOTTOM w0.102: v1(11.95,15.95) 12.2,16.2 12.2,21.69
PT26B: length 5.3
  BOTTOM w0.102: 12,21.69 12,16.83 11.95,16.78 v1(11.95,16.45)
PT27A: length 6.9
  L4_SIGNAL2 w0.102: 12.04,21.69 12.04,16.97 12.2,16.81 12.2,15.2 v1(11.95,14.95)
PT27B: length 7.4
  L4_SIGNAL2 w0.102: 11.84,21.69 11.84,16.96 11.7,16.82 11.7,14.7 v1(11.95,14.45)
PT27C: length 6.4
  BOTTOM w0.102: 11.65,21.69 11.65,15.75 v1(11.95,15.45)
PT27D: length 6.2
  BOTTOM w0.102: v1(11.45,15.45) 11.45,21.69
PT28A: length 5.3
  L3_SIGNAL1 w0.102: v2(11.45,16.45) 11.45,16.78 11.5,16.83 11.5,21.69
PT28B: length 5.8
  L3_SIGNAL1 w0.102: 11.7,21.69 11.7,16.2 v2(11.45,15.95)
PT32A: length 5.3
  L3_SIGNAL1 w0.102: v2(10.95,16.45) 10.95,16.78 11,16.83 11,21.69
PT32B: length 5.8
  L3_SIGNAL1 w0.102: v2(10.95,15.95) 11.2,16.2 11.2,21.69
PT33A: length 6.8
  BOTTOM w0.102: v1(11.45,14.95) 11.2,15.2 11.2,21.69
PT33B: length 6.3
  BOTTOM w0.102: 11,21.69 11,15.8 10.95,15.75 v1(10.95,15.45)
PT34A: length 7.4
  L4_SIGNAL2 w0.102: 11.05,21.69 11.05,15.8 11.2,15.65 11.2,14.7 v1(11.45,14.45)
PT34B: length 7.4
  L4_SIGNAL2 w0.102: v1(10.95,14.45) 10.7,14.7 10.7,15.65 10.85,15.8 10.85,21.69
PT35A: length 5.3
  L3_SIGNAL1 w0.102: v2(10.45,16.45) 10.45,16.78 10.5,16.83 10.5,21.69
PT35B: length 5.8
  L3_SIGNAL1 w0.102: v2(10.45,15.95) 10.7,16.2 10.7,21.69
PT36A: length 5.3
  L3_SIGNAL1 w0.102: v2(9.95,16.45) 9.95,16.78 10,16.83 10,21.69
PT36B: length 5.8
  L3_SIGNAL1 w0.102: v2(9.95,15.95) 10.2,16.2 10.2,21.69
PT36C: length 6.3
  BOTTOM w0.102: 10.5,21.69 10.5,15.8 10.45,15.75 v1(10.45,15.45)
PT36D: length 6.8
  BOTTOM w0.102: 10.7,21.69 10.7,15.2 v1(10.95,14.95)

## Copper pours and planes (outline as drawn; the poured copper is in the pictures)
GND on L2_GND: 3.53,3.45 3.53,21.74 11.15,21.74 11.15,13.65 13.26,13.65 13.26,21.74 21.77,21.74 21.74,3.45
VCC on L5_PWR: 3.53,16.97 3.53,21.74 13.39,21.74 13.39,13.89 14.07,13.21 14.07,11.99 11.53,11.99 11.53,12.95 11.81,13.23 11.81,13.77 9.55,13.77 6.35,16.97
VCCIO0 on L2_GND: 11.25,13.74 11.25,21.74 13.14,21.74 13.14,13.74
VCCIO1 on L5_PWR: 11.71,13.64 11.71,13.28 11.4,12.98 11.4,11.99 8.25,8.84 3.53,8.84 3.53,16.84 6.25,16.84 9.45,13.64
VCCIO2 on L5_PWR: 3.53,3.45 3.53,8.71 8.31,8.71 11.46,11.86 13.64,11.86 13.64,3.45
VCCIO3 on L5_PWR: 13.79,3.45 13.79,11.86 15.65,11.86 19.25,8.25 21.74,8.25 21.74,5.46 21.74,3.45
VCCIO4 on L5_PWR: 14.2,11.99 14.2,13.13 15.21,13.13 17.86,15.77 21.74,15.77 21.74,8.38 19.33,8.38 15.72,11.99
VCCIO5 on L5_PWR: 14.22,13.26 13.51,13.97 13.51,21.74 21.74,21.74 21.74,15.93 17.81,15.93 15.14,13.26

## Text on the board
User.Comments: R.P | REN | 09/03/14 | DWG NO: | XO3L-43E-256FCCSP | REVISION | 1.0 | SHEET | 1 | OF | LATTICE SEMICONDUCTOR CORPORATION | XO3L-43E-256FCCSP PCB BREAKOUT
Ref Des/Silkscreen Top: A | B | C | D | E | F | G | H | J | K | L | M | N | P | R | T | 1 | 2 | 3 | 4 | 5 | 6 | 7 | 8 | 9 | 10 | 11 | 12 | 13 | 14 | 15 | 16 | PCB BREAKOUT | XO3L-43E-256fcCSP | SEMICONDUCTOR | LATTICE
PAGE_OUTLINE: SPECIAL INSTRUCTIONS: | 1/2 OZ CU FOR EXTERNAL AND INTERNAL LAYERS | VIA IN PADS ARE TO BE NON CONDUCTIVE EXPOXY FILLED | BOTTOM SIDE    (L6) | BOTTOM SILKSCREEN | SIGNAL2        (L4) | BOTTOM SOLDERMASK | GND     PLANE  (L2) | SIGNAL1        (L3) | POWER   PLANE  (L5) | TOP SIDE       (L1) | TOP SOLDERMASK | TOP SILKSCREEN | DESIGNED BY: | APPROVED BY: | SIGNATURES         DATE | REV | 1 | INITIAL RELEASE | TRACE WIDTH/SPACE | ESCAPE VIA DRILL | ESCAPE VIA PAD | LAND OPENING | PACKAGE SIZE | LAND PAD | PITCH | DESCRIPTION | 0.102/0.097 | 0.1016 | 0.2032 | 9 x 9 | 0.3556 | 0.3048 | 0.50 | MM | MM/DD/YYYY | DATE | 354.3x354.3 | 4.00/3.80 | 8.00 | 14.00 | 4.00 | 12.00 | 19.69 | MILS | APPEOVED | X. XXXXX | 12 LAYER STACKUP | PCB BREAKOUT DETAILS | REVISION
DISPLAY_TOP: FIGURE | SIZE | 4.0 | DRILL CHART: TOP to L3_SIGNAL1 | ALL UNITS ARE IN MILS | PLATED | QTY | 97
DEVICE_TYPE_TOP: FIGURE | SIZE | 4.0 | DRILL CHART: TOP to BOTTOM | ALL UNITS ARE IN MILS | PLATED | QTY | 148
